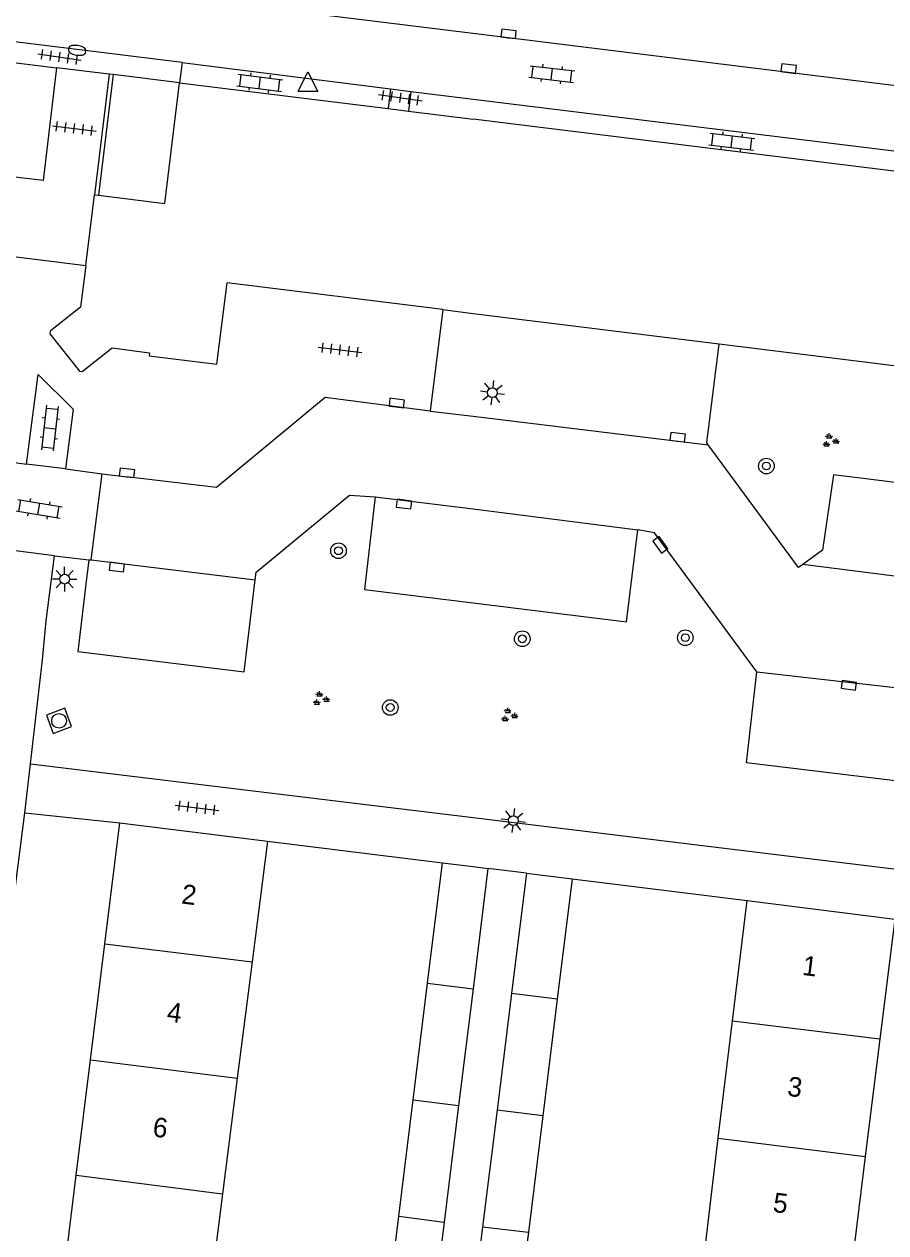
# Model space of a CAD drawing. Extents: x 131000 to 133014, y 396499 to 399001.
# Drawn here: x 131977 to 132021.2, y 396847.4 to 396909.4 of the extents above; entities that cross this region are included whole.
import ezdxf

# ---------------------------------------------------------------- set-up
doc = ezdxf.new("R2010")
doc.units = 0
for name, color, linetype in [('gg-afsc-muur', 7, 'Continuous'), ('gg-anno-huisnummerreeks BGT', 7, 'Continuous'), ('gg-bbg-bijgebouw', 7, 'Continuous'), ('gg-bbg-gedigitaliseerde bebouwing', 7, 'Continuous'), ('gg-bbg-gedigitaliseerde bijgebouw', 7, 'Continuous'), ('gg-bbg-hoofdgebouw', 7, 'Continuous'), ('gg-bbg-onder overbouw', 7, 'Continuous'), ('gg-bbg-pand overbouw', 7, 'Continuous'), ('gg-bbg-tussenscheiding', 7, 'Continuous'), ('gg-knt-verharding', 7, 'Continuous'), ('gg-knt-verharding nz', 7, 'Continuous'), ('gt-grn-weggrens', 7, 'Continuous'), ('gt-symb-boom', 7, 'Continuous'), ('gt-symb-brandkraan', 7, 'Continuous'), ('gt-symb-groenvak', 7, 'Continuous'), ('gt-symb-klinker verharding', 7, 'Continuous'), ('gt-symb-kolk', 7, 'Continuous'), ('gt-symb-lichtmast', 7, 'Continuous'), ('gt-symb-rioolschacht', 7, 'Continuous'), ('gt-symb-tegel verharding', 7, 'Continuous'), ('gt-symb-waterafsluiter', 7, 'Continuous')]:
    doc.layers.add(name, color=color, linetype=linetype)

# ---------------------------------------------------------------- blocks, each defined once
blk = doc.blocks.new('gt0-GRVAK')
at = {"layer": 'gt-symb-groenvak'}
for p, q in [((-0.11, 0.189), (-0.228, 0.24)), ((-0.182, 0.153), (0.088, 0.153)), ((-0.091, 0.211), (-0.156, 0.322)), ((-0.047, 0.214), (-0.047, 0.393)), ((-0.004, 0.211), (0.061, 0.322)), ((0.015, 0.189), (0.133, 0.24)), ((0.262, -0.052), (0.197, 0.059)), ((0.305, -0.049), (0.305, 0.13)), ((0.349, -0.052), (0.414, 0.059)), ((-0.245, -0.228), (-0.363, -0.177)), ((-0.318, -0.264), (-0.047, -0.264)), ((-0.226, -0.206), (-0.291, -0.095)), ((-0.183, -0.203), (-0.183, -0.024)), ((-0.139, -0.206), (-0.074, -0.095)), ((-0.12, -0.228), (-0.002, -0.177)), ((0.243, -0.074), (0.125, -0.023)), ((0.17, -0.11), (0.441, -0.11)), ((0.368, -0.074), (0.486, -0.023))]:
    blk.add_line(p, q, dxfattribs=at)
blk = doc.blocks.new('gt0-LMAST')
at = {"layer": 'gt-symb-lichtmast'}
for p, q in [((-0.005, 0.246), (-0.005, 0.621)), ((-0.182, 0.173), (-0.447, 0.438)), ((0.172, 0.173), (0.437, 0.438)), ((-0.255, -0.004), (-0.63, -0.004)), ((-0.182, -0.181), (-0.447, -0.446)), ((-0.005, -0.254), (-0.005, -0.629)), ((0.437, -0.446), (0.172, -0.181)), ((0.245, -0.004), (0.62, -0.004))]:
    blk.add_line(p, q, dxfattribs=at)
blk.add_circle((-0.005, -0.004), 0.25, dxfattribs=at)
blk = doc.blocks.new('gt0-BOOM')
at = {"layer": 'gt-symb-boom'}
for radius in [0.4, 0.2]:
    blk.add_circle((0, 0), radius, dxfattribs=at)
blk = doc.blocks.new('gt0-KOLK')
at = {"layer": 'gt-symb-kolk'}
blk.add_lwpolyline([(0, 0), (0.375, 0), (0.375, 0.4), (-0.375, 0.4), (-0.375, 0), (0, 0)], dxfattribs=at)
blk = doc.blocks.new('gt0-TEG1')
at = {"layer": 'gt-symb-tegel verharding'}
for p, q in [((-1.125, 0), (1.125, 0)), ((-0.9, -0.25), (-0.9, 0.25)), ((-0.45, -0.25), (-0.45, 0.25)), ((0, -0.25), (0, 0.25)), ((0.45, -0.25), (0.45, 0.25)), ((0.9, -0.25), (0.9, 0.25))]:
    blk.add_line(p, q, dxfattribs=at)
blk = doc.blocks.new('gt0-KL1')
at = {"layer": 'gt-symb-klinker verharding'}
for p, q in [((-1.15, 0.3), (1.15, 0.3)), ((-1, -0.3), (-1, 0.3)), ((-0.5, 0.3), (-0.5, 0.45)), ((0, -0.3), (0, 0.3)), ((0.5, 0.3), (0.5, 0.45)), ((1, -0.3), (1, 0.3)), ((-1.15, -0.3), (1.15, -0.3)), ((-0.5, -0.45), (-0.5, -0.3)), ((0.5, -0.45), (0.5, -0.3))]:
    blk.add_line(p, q, dxfattribs=at)
blk = doc.blocks.new('gt0-RS')
at = {"layer": 'gt-symb-rioolschacht'}
blk.add_lwpolyline([(-0.5, -0.5), (0.5, -0.5), (0.5, 0.5), (-0.5, 0.5)], close=True, dxfattribs=at)
blk.add_circle((0, 0), 0.375, dxfattribs=at)
blk = doc.blocks.new('gt0-WAFSL')
at = {"layer": 'gt-symb-waterafsluiter'}
for p, q in [((-0.5, -0.333), (0, 0.667)), ((0, 0.667), (0.5, -0.333)), ((0.5, -0.333), (-0.5, -0.333))]:
    blk.add_line(p, q, dxfattribs=at)
blk = doc.blocks.new('gt0-BR')
at = {"layer": 'gt-symb-brandkraan'}
for centre, radius, start, end in [((-0.244, 0), 0.206, 107.56694, 252.43307), ((0.599, -2.664), 3, 106.89205, 107.56694), ((0, -0.691), 0.938, 73.10799, 106.89205), ((-0.599, -2.664), 3, 72.43309, 73.10799), ((0.244, 0), 0.206, 287.56695, 72.43309), ((0.599, 2.664), 3, 252.43307, 253.10797), ((0, 0.691), 0.938, 253.10797, 286.89206), ((-0.599, 2.664), 3, 286.89206, 287.56695)]:
    blk.add_arc(centre, radius, start, end, dxfattribs=at)

msp = doc.modelspace()

# ---------------------------------------------------------------- linework, layer by layer
at = {"layer": 'gg-afsc-muur'}
for p, q in [((131981.341, 396906.793), (131980.59, 396900.61)), ((131981.549, 396906.767), (131980.797, 396900.585)), ((131989.46, 396867.48), (131998.434, 396866.372)), ((132005.073, 396865.55), (132014.04, 396864.44))]:
    msp.add_line(p, q, dxfattribs=at)
at = {"layer": 'gg-bbg-bijgebouw'}
for p, q in [((131998.434, 396866.372), (132000, 396866.178)), ((132000, 396866.178), (132000.756, 396866.084)), ((132002.731, 396865.84), (132005.073, 396865.55))]:
    msp.add_line(p, q, dxfattribs=at)
at = {"layer": 'gg-bbg-gedigitaliseerde bebouwing'}
for p, q in [((131989.46, 396867.48), (131988.671, 396861.302)), ((132013.295, 396858.282), (132014.04, 396864.44)), ((131988.671, 396861.302), (131987.91, 396855.338)), ((132012.567, 396852.264), (132013.295, 396858.282)), ((131987.91, 396855.338), (131987.153, 396849.408)), ((132011.851, 396846.354), (132012.567, 396852.264)), ((131987.153, 396849.408), (131986.39, 396843.431))]:
    msp.add_line(p, q, dxfattribs=at)
at = {"layer": 'gg-bbg-gedigitaliseerde bijgebouw'}
for p, q in [((131997.67, 396860.201), (131998.434, 396866.372)), ((132000.756, 396866.084), (132000, 396859.916)), ((132002.731, 396865.84), (132001.968, 396859.675)), ((132005.073, 396865.55), (132004.31, 396859.387)), ((131996.931, 396854.225), (131997.67, 396860.201)), ((132000, 396859.916), (131999.251, 396853.938)), ((132001.968, 396859.675), (132001.228, 396853.692)), ((132004.31, 396859.387), (132003.569, 396853.397)), ((131996.192, 396848.257), (131996.931, 396854.225)), ((131999.251, 396853.938), (131998.51, 396847.962)), ((132001.228, 396853.692), (132000.488, 396847.716)), ((132003.569, 396853.397), (132002.832, 396847.436)), ((131995.455, 396842.296), (131996.192, 396848.257)), ((131998.51, 396847.962), (131997.772, 396842.006)), ((132000.488, 396847.716), (131999.751, 396841.759)), ((132002.832, 396847.436), (132002.093, 396841.469))]:
    msp.add_line(p, q, dxfattribs=at)
at = {"layer": 'gg-bbg-hoofdgebouw'}
for p, q in [((131972.495, 396907.878), (131978.651, 396907.123)), ((131984.95, 396906.35), (131995.65, 396905.026)), ((131995.65, 396905.026), (131996.688, 396904.897)), ((131996.688, 396904.897), (132000, 396904.487)), ((132032.009, 396900.525), (132000, 396904.487)), ((131998.445, 396894.723), (131987.389, 396896.095)), ((131998.445, 396894.723), (132000, 396894.53)), ((132000, 396894.53), (132012.603, 396892.966)), ((132012.603, 396892.966), (132032.678, 396890.476)), ((131981.124, 396862.225), (131981.89, 396868.42)), ((131981.89, 396868.42), (131989.46, 396867.48)), ((132014.04, 396864.44), (132021.61, 396863.49)), ((132021.61, 396863.49), (132020.849, 396857.354)), ((131980.388, 396856.267), (131981.124, 396862.225)), ((132020.849, 396857.354), (132020.101, 396851.315)), ((131979.659, 396850.363), (131980.388, 396856.267)), ((132020.101, 396851.315), (132019.374, 396845.453)), ((131978.918, 396844.367), (131979.659, 396850.363))]:
    msp.add_line(p, q, dxfattribs=at)
msp.add_lwpolyline([(131980.149, 396896.98), (131979.886, 396894.849), (131978.318, 396893.62), (131978.304, 396893.488), (131979.821, 396891.563), (131979.966, 396891.558), (131981.51, 396892.762), (131982.148, 396892.681), (131982.759, 396892.597), (131983.423, 396892.509), (131983.399, 396892.347), (131986.87, 396891.93), (131987.389, 396896.095)], dxfattribs=at)
at = {"layer": 'gg-bbg-onder overbouw'}
for p, q in [((131980.149, 396896.98), (131980.59, 396900.61)), ((131980.59, 396900.61), (131980.797, 396900.585))]:
    msp.add_line(p, q, dxfattribs=at)
for points in [[(131978.651, 396907.123), (131977.967, 396901.339), (131975.2, 396901.671), (131975.263, 396902.317), (131971.844, 396902.729)], [(131980.797, 396900.585), (131984.21, 396900.17), (131984.95, 396906.35)]]:
    msp.add_lwpolyline(points, dxfattribs=at)
at = {"layer": 'gg-bbg-pand overbouw'}
for p, q in [((131981.341, 396906.793), (131978.651, 396907.123)), ((131981.549, 396906.767), (131981.341, 396906.793)), ((131984.95, 396906.35), (131981.549, 396906.767)), ((131971.27, 396898.08), (131980.149, 396896.98))]:
    msp.add_line(p, q, dxfattribs=at)
at = {"layer": 'gg-bbg-tussenscheiding'}
for p, q in [((131981.124, 396862.225), (131988.671, 396861.302)), ((131997.67, 396860.201), (132000, 396859.916)), ((132004.31, 396859.387), (132001.968, 396859.675)), ((132013.295, 396858.282), (132020.849, 396857.354)), ((131980.388, 396856.267), (131987.91, 396855.338)), ((131996.931, 396854.225), (131999.251, 396853.938)), ((132003.569, 396853.397), (132001.228, 396853.692)), ((132012.567, 396852.264), (132020.101, 396851.315)), ((131979.659, 396850.363), (131987.153, 396849.408)), ((131996.192, 396848.257), (131998.51, 396847.962)), ((132000.488, 396847.716), (132002.832, 396847.436))]:
    msp.add_line(p, q, dxfattribs=at)
at = {"layer": 'gg-knt-verharding'}
for p, q in [((131985.084, 396907.391), (131984.95, 396906.35)), ((131985.084, 396907.391), (131995.775, 396906.033)), ((131995.775, 396906.033), (131995.65, 396905.026)), ((131995.775, 396906.033), (131996.813, 396905.909)), ((131996.813, 396905.909), (131996.688, 396904.897)), ((131996.813, 396905.909), (132032.136, 396901.548)), ((131998.445, 396894.723), (131997.801, 396889.527)), ((131976.504, 396886.88), (131977.111, 396886.808)), ((131979.119, 396886.561), (131980.991, 396886.31)), ((131980.429, 396881.902), (131980.991, 396886.31)), ((131980.991, 396886.31), (131982.239, 396886.161)), ((131978.113, 396878.773), (131978.544, 396882.106)), ((131978.544, 396882.106), (131980.304, 396881.907)), ((131980.304, 396881.907), (131980.156, 396880.646)), ((131980.304, 396881.907), (131980.429, 396881.902)), ((131977.02, 396868.94), (131977.312, 396871.451)), ((131977.312, 396871.451), (132000, 396868.687)), ((131976.553, 396865.181), (131977.02, 396868.94)), ((131977.02, 396868.94), (131981.89, 396868.42)), ((132000, 396868.687), (132026.726, 396865.431))]:
    msp.add_line(p, q, dxfattribs=at)
for points in [[(132028.855, 396905.296), (132001.793, 396908.661), (131981.795, 396911.128)], [(131985.084, 396907.391), (131972.623, 396908.922), (131972.495, 396907.878)], [(132012.046, 396887.793), (132011.974, 396887.891), (132012.603, 396892.966)], [(131977.111, 396886.808), (131977.716, 396891.406), (131979.503, 396889.617), (131979.119, 396886.561)], [(131997.801, 396889.527), (131992.425, 396890.227), (131986.857, 396885.615), (131982.239, 396886.161)], [(132016.897, 396881.668), (132016.675, 396881.507), (132012.046, 396887.793)], [(132026.632, 396880.42), (132027.288, 396885.158), (132018.471, 396886.252), (132017.899, 396882.391), (132016.897, 396881.668)], [(131988.829, 396880.881), (131988.875, 396881.266), (131993.671, 396885.217), (131994.986, 396885.13)], [(131994.986, 396885.13), (131994.439, 396880.387), (132000, 396879.696)], [(132000, 396879.696), (132007.856, 396878.72), (132008.44, 396883.441)], [(132014.541, 396876.159), (132009.302, 396883.284), (132008.44, 396883.441)], [(131980.156, 396880.646), (131979.739, 396877.196), (131988.271, 396876.162), (131988.829, 396880.881)], [(131977.312, 396871.451), (131977.932, 396876.776), (131978.113, 396878.773)], [(132023.088, 396875.191), (132022.49, 396870.47), (132014.017, 396871.493), (132014.541, 396876.159)]]:
    msp.add_lwpolyline(points, dxfattribs=at)
at = {"layer": 'gg-knt-verharding nz'}
for p, q in [((131997.801, 396889.527), (132000, 396889.259)), ((132000, 396889.259), (132012.046, 396887.793)), ((131994.986, 396885.13), (132000, 396884.512)), ((132000, 396884.512), (132008.44, 396883.441)), ((131980.429, 396881.902), (131988.829, 396880.881)), ((132026.632, 396880.42), (132016.897, 396881.668)), ((132014.541, 396876.159), (132023.088, 396875.191))]:
    msp.add_line(p, q, dxfattribs=at)
at = {"layer": 'gt-grn-weggrens'}
for p, q in [((131979.119, 396886.561), (131977.111, 396886.808)), ((131978.544, 396882.106), (131976.54, 396882.364)), ((132002.731, 396865.84), (132000.756, 396866.084))]:
    msp.add_line(p, q, dxfattribs=at)

# ---------------------------------------------------------------- block references
at = {"layer": 'gt-symb-boom'}
for p in [(132015.03, 396886.708), (131993.101, 396882.366), (132002.522, 396877.854), (132010.878, 396877.91), (131995.752, 396874.331)]:
    msp.add_blockref('gt0-BOOM', p, dxfattribs=at)
at = {"layer": 'gt-symb-brandkraan', "rotation": -8.57744906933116}
msp.add_blockref('gt0-BR', (131979.709, 396908.012), dxfattribs=at)
at = {"layer": 'gt-symb-groenvak'}
for p in [(132018.296, 396888.004), (131992.176, 396874.774), (132001.826, 396873.93)]:
    msp.add_blockref('gt0-GRVAK', p, dxfattribs=at)
at = {"layer": 'gt-symb-klinker verharding'}
for p, rotation in [((132004.033, 396906.796), -6.606034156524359), ((131989.07, 396906.352), -7.238726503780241), ((132013.26, 396903.329), -7.068140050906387), ((131978.307, 396888.654), -96.14399576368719), ((131977.751, 396884.514), -9.500010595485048)]:
    msp.add_blockref('gt0-KL1', p, dxfattribs=dict(at, rotation=rotation))
at = {"layer": 'gt-symb-kolk'}
for p, rotation in [((132001.793, 396908.661), -7.086981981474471), ((132016.15, 396906.876), -7.086981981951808), ((131996.064, 396889.738), -6.947410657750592), ((132010.458, 396887.986), -6.947410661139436), ((131982.239, 396886.161), -6.776782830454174), ((131996.483, 396884.958), 173.1663276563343), ((132009.753, 396882.788), 126.13684490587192), ((131981.765, 396881.728), 172.7612734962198), ((132019.283, 396875.667), 172.8749836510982)]:
    msp.add_blockref('gt0-KOLK', p, dxfattribs=dict(at, rotation=rotation))
at = {"layer": 'gt-symb-lichtmast'}
for p, rotation in [((132000.997, 396890.467), -7.295560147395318), ((132002.068, 396868.541), -7.068140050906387)]:
    msp.add_blockref('gt0-LMAST', p, dxfattribs=dict(at, rotation=rotation))
msp.add_blockref('gt0-LMAST', (131979.072, 396880.914), dxfattribs=at)
at = {"layer": 'gt-symb-rioolschacht', "rotation": -159.64503881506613}
msp.add_blockref('gt0-RS', (131978.78, 396873.649), dxfattribs=at)
at = {"layer": 'gt-symb-tegel verharding'}
for p, rotation in [((131978.8, 396907.67), -8.45426172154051), ((131996.273, 396905.584), -8.105793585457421), ((131979.558, 396904.012), -7.068140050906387), ((131993.182, 396892.663), -7.068140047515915), ((131985.848, 396869.191), -7.068140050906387)]:
    msp.add_blockref('gt0-TEG1', p, dxfattribs=dict(at, rotation=rotation))
at = {"layer": 'gt-symb-waterafsluiter'}
msp.add_blockref('gt0-WAFSL', (131991.535, 396906.241), dxfattribs=at)

# ---------------------------------------------------------------- texts
at = {"layer": 'gg-anno-huisnummerreeks BGT'}
for s, p in [('2', (131985.019, 396864.293)), ('1', (132016.833, 396860.631)), ('4', (131984.272, 396858.249)), ('3', (132016.066, 396854.437)), ('6', (131983.544, 396852.354)), ('5', (132015.328, 396848.487))]:
    msp.add_text(s, height=1, rotation=352.9, dxfattribs=at).set_placement(p)

doc.saveas('drawing.dxf')
